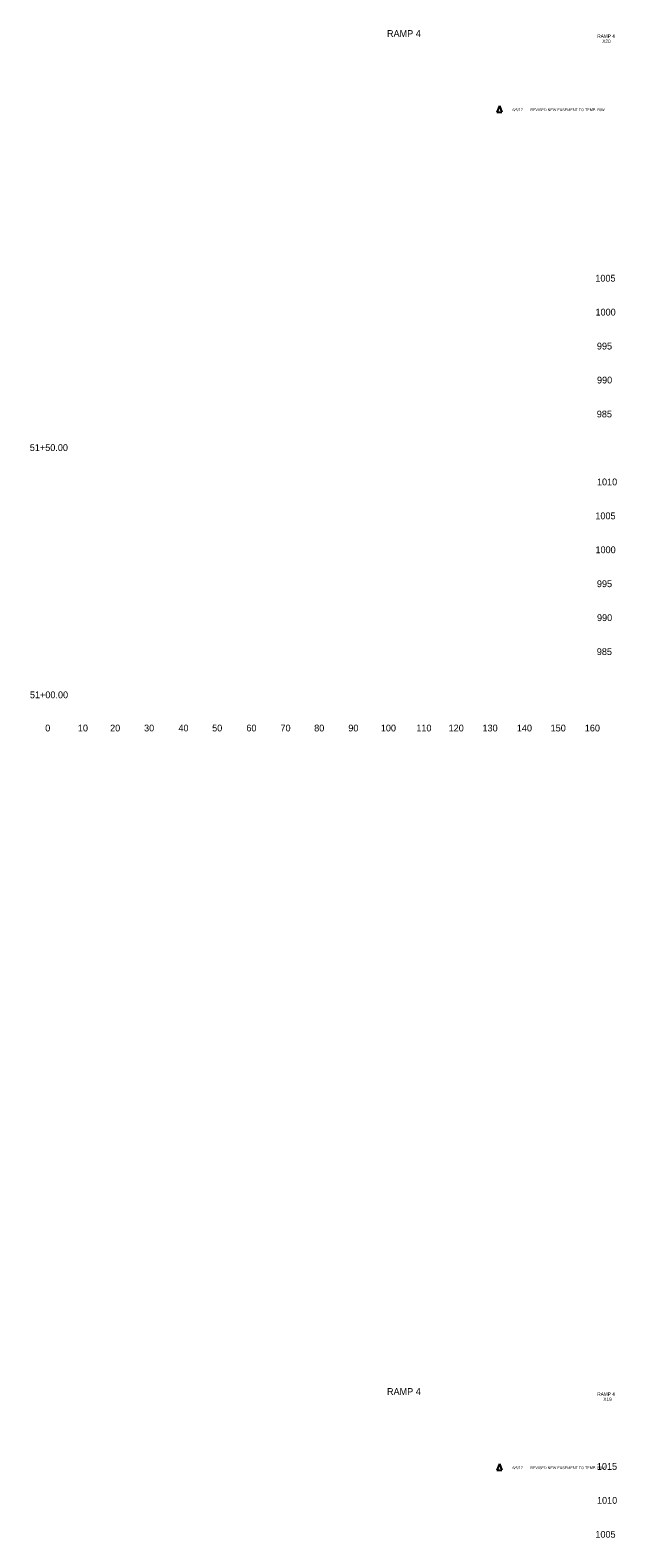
# Model space of a CAD drawing. Extents: x 4994 to 6872, y 4997 to 8804.
# Drawn here: x 5669.9 to 5842.5, y 8360 to 8804.1 of the extents above; entities that cross this region are included whole.
import ezdxf

# ---------------------------------------------------------------- set-up
doc = ezdxf.new("R2010")
doc.units = 0
for name, color, linetype in [('RD_SHT_ID', 7, 'Continuous'), ('RD_SHT_TX', 7, 'Continuous'), ('RD_XS_TX_Offset', 7, 'Continuous'), ('RD_XS_TX_Station', 7, 'Continuous')]:
    doc.layers.add(name, color=color, linetype=linetype)

msp = doc.modelspace()

# ---------------------------------------------------------------- linework, layer by layer
at = {"layer": 'RD_SHT_TX'}
for p, q in [((5807.95, 8781.77), (5807.24, 8779.94)), ((5807.24, 8779.94), (5808.67, 8779.94)), ((5807.95, 8781.77), (5808.67, 8779.94)), ((5807.95, 8381.77), (5807.24, 8379.94)), ((5807.95, 8381.77), (5808.67, 8379.94)), ((5807.24, 8379.94), (5808.67, 8379.94))]:
    msp.add_line(p, q, dxfattribs=at)

# ---------------------------------------------------------------- texts
at = {"layer": 'RD_SHT_ID'}
for s, height, p in [('RAMP 4', 2, (5774.88, 8802.06)), ('RAMP 4', 1, (5836.78, 8801.8)), ('X20', 1, (5838.25, 8800.3)), ('RAMP 4', 2, (5774.88, 8402.06)), ('RAMP 4', 1, (5836.78, 8401.8)), ('X19', 1, (5838.57, 8400.3))]:
    msp.add_text(s, height=height, dxfattribs=at).set_placement(p)
at = {"layer": 'RD_SHT_TX'}
for s, p in [('1', (5807.95, 8780.24)), ('6/5/17', (5811.82, 8780.21)), ('REVISED NEW EASEMENT TO TEMP. R/W', (5817.05, 8780.21)), ('1', (5807.95, 8380.24)), ('6/5/17', (5811.82, 8380.21)), ('REVISED NEW EASEMENT TO TEMP. R/W', (5817.05, 8380.21))]:
    msp.add_text(s, height=0.792, dxfattribs=at).set_placement(p)
at = {"layer": 'RD_XS_TX_Offset'}
for s, p in [('1005', (5836.2, 8730)), ('1000', (5836.24, 8720)), ('995', (5836.66, 8710)), ('990', (5836.69, 8700)), ('985', (5836.63, 8690)), ('1010', (5836.68, 8670)), ('1005', (5836.2, 8660)), ('1000', (5836.24, 8650)), ('995', (5836.66, 8640)), ('990', (5836.69, 8630)), ('985', (5836.63, 8620)), ('0', (5674.3, 8597.5)), ('0', (5674.3, 8597.5)), ('10', (5683.91, 8597.5)), ('20', (5693.4, 8597.5)), ('30', (5703.39, 8597.5)), ('40', (5713.5, 8597.5)), ('50', (5723.43, 8597.5)), ('60', (5733.5, 8597.5)), ('70', (5743.54, 8597.5)), ('80', (5753.46, 8597.5)), ('90', (5763.5, 8597.5)), ('100', (5773.07, 8597.5)), ('110', (5783.51, 8597.5)), ('120', (5793.01, 8597.5)), ('130', (5802.99, 8597.5)), ('140', (5813.1, 8597.5)), ('150', (5823.04, 8597.5)), ('160', (5833.1, 8597.5)), ('1015', (5836.65, 8380)), ('1010', (5836.68, 8370)), ('1005', (5836.2, 8360))]:
    msp.add_text(s, height=2, dxfattribs=at).set_placement(p)
at = {"layer": 'RD_XS_TX_Station'}
for s, p in [('51+50.00', (5669.76, 8680.11)), ('51+00.00', (5669.8, 8607.28))]:
    msp.add_text(s, height=2, dxfattribs=at).set_placement(p)

doc.saveas('drawing.dxf')
